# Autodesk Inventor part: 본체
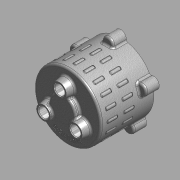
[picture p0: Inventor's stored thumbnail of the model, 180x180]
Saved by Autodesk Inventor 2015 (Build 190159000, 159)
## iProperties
Created: 2015-11
Part Number: 본체
Document SubType Name: 모델링
Designer: mdu
Material: 알루미늄 6061
Density: 2.71 g/cm^3
Appearance: 알루미늄 - 평지
Mass: 487.639 g
Surface Area: 696.801 cm^2
Volume: 179.94 cm^3
변환 표준: STEP AP214IS
파일 이름: C:\Users\SeoGD\Desktop\?쒗뿕\紐몄껜.stp
전처리기: Build: 253, Release: 2010 SP1 - Date: Wed 07/29/2009
전송 단위: 밀리미터
불확실성: 0.01
Author: mdu
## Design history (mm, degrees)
sketch "스케치2"
  geometry: C1 r 50 at (0, 0); 1 further point
  constraints: 1 centre point, 1 coincident
  dimensions: "d9" = 100 diameter of C1
extrude "돌출2" new body sketch "스케치2" distance "d10" = 80; taper "d11" = 0 deg
feature "쉘1" dims "d12" = 5
sketch "스케치3" dims "d13" = 55
  geometry: C1 r 7.5 at (0, 27.5); C2 r 12.5 at (0, 27.5); 2 further points
  constraints: 2 centre point, 2 coincident, 2 vertical alignment, 2 other
  dimensions: "d14" = 15 diameter of C1; "d15" = 25 diameter of C2
extrude "돌출3" join sketch "스케치3" distance "d16" = 12; taper "d17" = -10 deg
hole "구멍2" diameter "d20" = 15; stored, may be unused: countersink angle "d24" = 90 deg, drill point angle "d26" = 118 deg; dims "d18" = 10, "d19" = 10, "d21" = 6, "d22" = 4, "d23" = 2, "d25" = 15
chamfer "모따기1" distance "d27" = 1; stored, may be unused: second distance "d28" = 2, angle "d29" = 45 deg
sketch "스케치4"
  geometry: L1 (0, 0)-(0, 88); L2 (0, 70)-(13.16, 70); L3 (-45, 75)-(45, 75) reference; L4 (-50, 80)-(50, 80) reference; L5 (13.16, 70)-(14.5, 75); L6 (20, 80)-(20, 88); L7 (20, 88)-(0, 88); L8 (20, 80)-(14.5, 75)
  constraints: 12 end point, 3 point on line, 2 perpendicular, 1 vertical
  dimensions: "d34" = 40 diameter of L6 L1; "d35" = 105 deg angle of L5 L3; "d36" = 5 distance between parallel lines of L2 L3; "d37" = 8 distance between parallel lines of L7 L4; "d51" = 29 diameter of L5.end L1
revolve "회전1" sketch "스케치4" stored, may be unused: angle "d38" = 90 deg
hole "구멍3" diameter "d41" = 15; stored, may be unused: countersink angle "d45" = 90 deg, drill point angle "d47" = 0 deg; dims "d39" = 10, "d40" = 10, "d42" = 6, "d43" = 22, "d44" = 13, "d46" = 15
chamfer "모따기2" distance "d48" = 1; stored, may be unused: second distance "d49" = 2, angle "d50" = 45 deg
fillet "모깎기1" dims "d52" = 3
fillet "모깎기2" dims "d53" = 3, "d72" = 0.2
sketch "스케치5"
  geometry: A1 r 50 centre (0, 0) between (50, 0) and (-8.074, 49.344) reference; A2 r 8.5 centre (0, 52) between (8.074, 49.344) and (-8.074, 49.344); 1 further point
  constraints: 5 point on circle, 1 centre point, 1 horizontal alignment
  dimensions: "d54" = 90 deg dimension on point (0, 0) A2.centre A1.start; "d55" = 52 distance of A2.centre point (0, 0); "d56" = 17 diameter of A2
extrude "돌출4" join sketch "스케치5" distance "d57" = 20; taper "d58" = 0 deg
fillet "모깎기3" dims "d59" = 3
hole "구멍4" diameter "d62" = 4.134; stored, may be unused: countersink angle "d66" = 90 deg, drill point angle "d68" = 118 deg; dims "d60" = 10, "d61" = 10, "d63" = 12, "d64" = 22, "d65" = 13, "d67" = 15
sketch "스케치6"
  geometry: C1 r 47 at (0, 0) reference; C2 r 42.5 at (0, 0); 1 further point
  constraints: 1 centre point, 1 coincident, 1 other
  dimensions: "d73" = 85 diameter of C2
feature "엠보싱1" sketch "스케치6" dims "d74" = 0.5, "d75" = 0
node "작업 평면1"
sketch "스케치7"
  geometry: A1 r 50 centre (0, 0) between (5.144, 49.735) and (-5.144, 49.735) reference; A2 r 3 centre (0, 47.916) between (2.204, 49.951) and (-2.204, 49.951); 1 further point
  constraints: 4 point on circle, 1 centre point, 1 vertical alignment
  dimensions: "d77" = 3 radius of A2
extrude "돌출5" join sketch "스케치7" distance "d79" = 15; taper "d80" = 0 deg
fillet "모깎기4" dims "d81" = 1
fillet "모깎기5" dims "d82" = 1
node "솔리드1"
node "솔리드 본체"
node "곡면 본체"
pattern_circular "원형 패턴1" dims "d31" = 360 deg
pattern_circular "원형 패턴2" dims "d70" = 360 deg
pattern_circular "원형 패턴3" dims "d84" = 360 deg
pattern_linear "직사각형 패턴1" dims "d89" = 25
node "솔리드2"
